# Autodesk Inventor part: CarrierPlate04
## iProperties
Created: 2008-02
Part Number: CarrierPlate04
Document SubType Name: Modeling
Designer: grh
Density: 1 g/cm^3
Author: grh
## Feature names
1. Extrusion1
